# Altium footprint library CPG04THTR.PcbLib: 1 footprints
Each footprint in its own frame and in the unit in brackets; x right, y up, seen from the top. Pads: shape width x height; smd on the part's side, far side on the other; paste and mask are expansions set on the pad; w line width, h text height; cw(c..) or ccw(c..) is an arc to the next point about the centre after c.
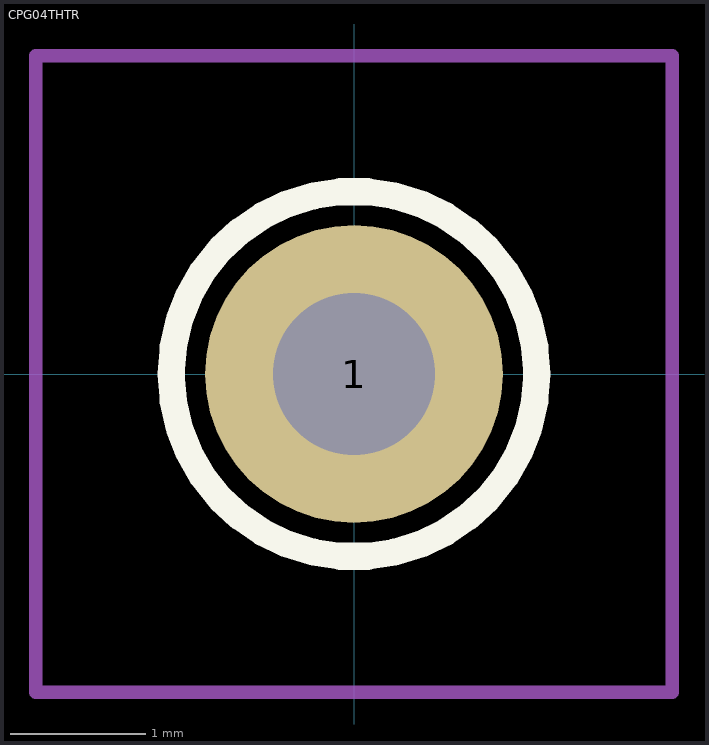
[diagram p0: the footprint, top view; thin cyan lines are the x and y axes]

## CPG04THTR [mm]
pads (1):
  round 2.2 hole 1.2: 1(0,0)
Top Overlay:
  lines w0.2: -1.35,0 -1.35,0 ; -1.35,0 ccw(c0,0) 1.35,0 ; -1.35,0 cw(c0,0) 1.35,0 ; 1.35,0 1.35,0
Mechanical 15:
  lines w0.1: -1.35,0 -1.35,0 ; -1.35,0 ccw(c0,0) 1.35,0 ; -1.35,0 cw(c0,0) 1.35,0 ; 1.35,0 1.35,0
Mechanical 20:
  lines w0.1: -2.35,-2.35 2.35,-2.35 2.35,2.35 -2.35,2.35 -2.35,-2.35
